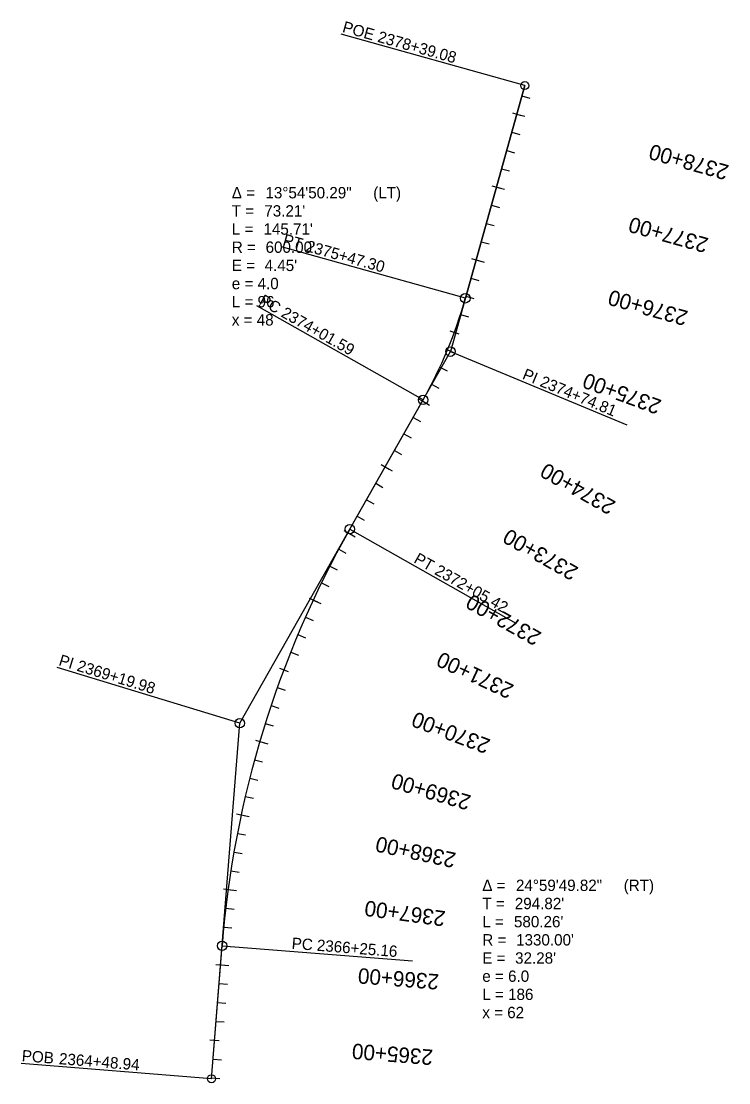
# Model space of a CAD drawing. Extents: x 20506511 to 20507445, y 7969244 to 7970646.
import ezdxf

# ---------------------------------------------------------------- set-up
doc = ezdxf.new("R2010")
doc.units = 0
for name, color, linetype in [('Alignment', 7, 'Continuous'), ('TextAlignment', 7, 'Continuous'), ('TextAlignmentLrg', 7, 'Continuous'), ('TextAlignmentSml', 7, 'Continuous')]:
    doc.layers.add(name, color=color, linetype=linetype)

msp = doc.modelspace()

# ---------------------------------------------------------------- linework, layer by layer
at = {"layer": 'Alignment'}
for p, q in [((20507175.7, 7970561.2), (20507077.5, 7970209.7)), ((20507175.7, 7970561.2), (20507097.2, 7970280.2)), ((20507097.2, 7970280.2), (20507175.7, 7970561.2)), ((20506799.4, 7969718.8), (20507077.5, 7970209.7)), ((20506944.7, 7969975.3), (20507041.4, 7970146)), ((20506762.1, 7969249.2), (20506799.4, 7969718.8)), ((20506762.1, 7969249.2), (20506776.1, 7969424.9)), ((20506762.1, 7969249.2), (20506776.1, 7969424.9))]:
    msp.add_line(p, q, dxfattribs=at)
for centre, radius, start, end in [((20506519.3, 7970441.7), 600, 330.4678, 344.3818), ((20506519.3, 7970441.7), 600, 330.4678, 344.3818), ((20508101.9, 7969319.7), 1330, 150.4678, 175.465), ((20508101.9, 7969319.7), 1330, 150.4678, 175.465)]:
    msp.add_arc(centre, radius, start, end, dxfattribs=at)
at = {"layer": 'TextAlignment'}
for p, q in [((20507175.7, 7970561.2), (20506933.1, 7970629)), ((20506933.1, 7970629), (20506933.1, 7970629)), ((20507097.2, 7970280.2), (20506854.5, 7970348)), ((20506854.5, 7970348), (20506854.5, 7970348)), ((20507041.4, 7970146), (20506822.1, 7970270.2)), ((20506822.1, 7970270.2), (20506822.1, 7970270.2)), ((20507077.5, 7970209.7), (20507310.2, 7970112.9)), ((20507310.2, 7970112.9), (20507310.2, 7970112.9)), ((20506944.7, 7969975.3), (20507164, 7969851.1)), ((20507164, 7969851.1), (20507164, 7969851.1)), ((20506799.4, 7969718.8), (20506558.4, 7969792.6)), ((20506558.4, 7969792.6), (20506558.4, 7969792.6)), ((20506776.1, 7969424.9), (20507027.3, 7969404.9)), ((20507027.3, 7969404.9), (20507027.3, 7969404.9)), ((20506762.1, 7969249.2), (20506510.9, 7969269.1)), ((20506510.9, 7969269.1), (20506510.9, 7969269.1))]:
    msp.add_line(p, q, dxfattribs=at)
for centre, radius in [((20507175.7, 7970561.2), 5.34), ((20507097.2, 7970280.2), 6.24), ((20507077.5, 7970209.7), 6.24), ((20507041.4, 7970146), 6.24), ((20506944.7, 7969975.3), 6.24), ((20506799.4, 7969718.8), 6.24), ((20506776.1, 7969424.9), 6.24), ((20506762.1, 7969249.2), 5.34)]:
    msp.add_circle(centre, radius, dxfattribs=at)
at = {"layer": 'TextAlignmentLrg'}
for p, q in [((20507165.2, 7970523.6), (20507175.7, 7970520.6)), ((20507138.3, 7970427.2), (20507148.8, 7970424.3)), ((20507111.4, 7970330.9), (20507121.9, 7970328)), ((20507076.9, 7970237.3), (20507088.4, 7970233.1)), ((20507040.6, 7970144.6), (20507050.1, 7970139.2)), ((20506991.3, 7970057.6), (20507000.8, 7970052.2)), ((20506942, 7969970.6), (20506951.6, 7969965.2)), ((20506896.4, 7969881.6), (20506906.3, 7969877)), ((20506851.9, 7969791.6), (20506863.3, 7969787.3)), ((20506825.8, 7969694.7), (20506836.3, 7969691.6)), ((20506801.3, 7969597.8), (20506812, 7969595.5)), ((20506784.1, 7969499.3), (20506794.9, 7969497.8)), ((20506774.1, 7969399.8), (20506785, 7969398.9)), ((20506760.1, 7969300.6), (20506772.3, 7969299.6))]:
    msp.add_line(p, q, dxfattribs=at)
at = {"layer": 'TextAlignmentSml'}
for p, q in [((20507172, 7970547.6), (20507182.5, 7970544.7)), ((20507159.3, 7970525.2), (20507171.1, 7970521.9)), ((20507158.5, 7970499.5), (20507169, 7970496.5)), ((20507151.8, 7970475.4), (20507162.3, 7970472.5)), ((20507145, 7970451.3), (20507155.5, 7970448.4)), ((20507132.4, 7970428.9), (20507144.2, 7970425.6)), ((20507131.6, 7970403.2), (20507142.1, 7970400.2)), ((20507124.8, 7970379.1), (20507135.4, 7970376.2)), ((20507118.1, 7970355), (20507128.6, 7970352.1)), ((20507105.5, 7970332.6), (20507117.3, 7970329.3)), ((20507104.6, 7970306.9), (20507115.2, 7970303.9)), ((20507097.9, 7970282.8), (20507108.4, 7970279.8)), ((20507090.8, 7970258.8), (20507101.2, 7970255.5)), ((20507076.9, 7970237.3), (20507088.4, 7970233.1)), ((20507073.6, 7970211.9), (20507083.7, 7970207.7)), ((20507063.5, 7970189), (20507073.4, 7970184.4)), ((20507052.5, 7970166.6), (20507062.2, 7970161.6)), ((20507035.3, 7970147.6), (20507045.9, 7970141.6)), ((20507028.3, 7970122.8), (20507037.8, 7970117.5)), ((20507016, 7970101.1), (20507025.5, 7970095.7)), ((20507003.6, 7970079.3), (20507013.1, 7970073.9)), ((20506986, 7970060.6), (20506996.6, 7970054.6)), ((20506979, 7970035.8), (20506988.5, 7970030.4)), ((20506966.7, 7970014.1), (20506976.2, 7970008.7)), ((20506954.3, 7969992.3), (20506963.8, 7969986.9)), ((20506936.7, 7969973.6), (20506947.4, 7969967.6)), ((20506930, 7969948.7), (20506939.6, 7969943.5)), ((20506918.4, 7969926.5), (20506928.1, 7969921.5)), ((20506907.2, 7969904.2), (20506917, 7969899.4)), ((20506890.9, 7969884.2), (20506902, 7969879)), ((20506886.1, 7969858.8), (20506896.1, 7969854.4)), ((20506876.2, 7969835.9), (20506886.2, 7969831.7)), ((20506866.7, 7969812.8), (20506876.8, 7969808.7)), ((20506851.9, 7969791.6), (20506863.3, 7969787.3)), ((20506849, 7969766), (20506859.3, 7969762.3)), ((20506840.8, 7969742.4), (20506851.2, 7969738.9)), ((20506833.1, 7969718.6), (20506843.5, 7969715.3)), ((20506820, 7969696.4), (20506831.7, 7969692.9)), ((20506819, 7969670.6), (20506829.6, 7969667.7)), ((20506812.7, 7969646.4), (20506823.2, 7969643.8)), ((20506806.7, 7969622.2), (20506817.4, 7969619.7)), ((20506795.3, 7969599), (20506807.3, 7969596.5)), ((20506796.3, 7969573.3), (20506807, 7969571.2)), ((20506791.8, 7969548.7), (20506802.5, 7969546.8)), ((20506787.7, 7969524), (20506798.5, 7969522.3)), ((20506778, 7969500.1), (20506790.1, 7969498.4)), ((20506780.9, 7969474.5), (20506791.8, 7969473.2)), ((20506778.3, 7969449.6), (20506789.1, 7969448.5)), ((20506776.1, 7969424.7), (20506786.9, 7969423.8)), ((20506768, 7969400.3), (20506780.2, 7969399.3)), ((20506772.1, 7969374.9), (20506783, 7969374)), ((20506770.1, 7969349.9), (20506781, 7969349.1)), ((20506768.1, 7969325), (20506779, 7969324.2)), ((20506760.1, 7969300.6), (20506772.3, 7969299.6)), ((20506764.2, 7969275.2), (20506775.1, 7969274.3)), ((20506762.2, 7969250.3), (20506773.1, 7969249.4))]:
    msp.add_line(p, q, dxfattribs=at)

# ---------------------------------------------------------------- texts
at = {"layer": 'TextAlignment'}
for s, rotation, p in [('POE ', 344.3818, (20506933.9, 7970632.2)), ('2378+39.08', 344.3818, (20506980.3, 7970619.2)), ('PT', 344.3818, (20506855.4, 7970351.2)), ('2375+47.30', 344.3818, (20506885.7, 7970342.7)), ('PC', 330.4678, (20506823.8, 7970273.1)), ('2374+01.59', 330.4678, (20506852.7, 7970256.6)), ('PI ', 337.4248, (20507171.4, 7970174.2)), ('2374+74.81', 337.4248, (20507194.5, 7970164.6)), ('PT', 330.4678, (20507028.1, 7969931.8)), ('2372+05.42', 330.4678, (20507055.5, 7969916.3)), ('PI ', 342.9664, (20506559.4, 7969795.7)), ('2369+19.98', 342.9664, (20506583.3, 7969788.4)), ('PC', 355.465, (20506867.5, 7969420.9)), ('2366+25.16', 355.465, (20506900.7, 7969418.3)), ('POB ', 355.465, (20506511.2, 7969272.4)), ('2364+48.94', 355.465, (20506560.3, 7969268.5))]:
    msp.add_text(s, height=15, rotation=rotation, dxfattribs=at).set_placement(p)
for s, p in [(' (LT)', (20506970, 7970412.2)), ('Δ = ', (20506788.9, 7970412.2)), ('13°54\'50.29"', (20506833.3, 7970412.2)), ('T = ', (20506788.9, 7970388.2)), ("73.21'", (20506831.8, 7970388.2)), ('L = ', (20506788.9, 7970364.2)), ("145.71'", (20506830.7, 7970364.2)), ('R = ', (20506788.9, 7970340.2)), ("600.00'", (20506833.5, 7970340.2)), ('E = ', (20506788.9, 7970316.2)), ("4.45'", (20506832.2, 7970316.2)), ('e = 4.0', (20506788.9, 7970292.2)), ('L = 96', (20506788.9, 7970268.2)), ('x = 48', (20506788.9, 7970244.2)), ('Δ = ', (20507119.6, 7969497.2)), ('24°59\'49.82"', (20507164, 7969497.2)), (' (RT)', (20507300.7, 7969497.2)), ("294.82'", (20507162.5, 7969473.2)), ('T = ', (20507119.6, 7969473.2)), ('L = ', (20507119.6, 7969449.2)), ("580.26'", (20507161.4, 7969449.2)), ('R = ', (20507119.6, 7969425.2)), ("1330.00'", (20507164.2, 7969425.2)), ('E = ', (20507119.6, 7969401.2)), ("32.28'", (20507162.9, 7969401.2)), ('e = 6.0', (20507119.6, 7969377.2)), ('L = 186', (20507119.6, 7969353.2)), ('x = 62', (20507119.6, 7969329.2))]:
    msp.add_text(s, height=15, dxfattribs=at).set_placement(p)
at = {"layer": 'TextAlignmentLrg'}
for s, rotation, p in [('2375+00', 159.8651, (20507357.5, 7970145.3)), ('2370+00', 159.3172, (20507131.6, 7969696.9)), ('2365+00', 175.465, (20507055.1, 7969287.4))]:
    msp.add_text(s, height=20.4, rotation=rotation, dxfattribs=at).set_placement(p)
at = {"layer": 'TextAlignmentSml'}
for s, rotation, p in [('2378+00', 164.3818, (20507446.3, 7970455.6)), ('2377+00', 164.3818, (20507419.4, 7970359.3)), ('2376+00', 164.3818, (20507392.4, 7970263)), ('2375+00', 159.8651, (20507357.5, 7970145.3)), ('2374+00', 150.4678, (20507297.1, 7970011)), ('2373+00', 150.4678, (20507247.8, 7969924)), ('2372+00', 150.7013, (20507199, 7969838)), ('2371+00', 155.0093, (20507162.7, 7969768.8)), ('2370+00', 159.3172, (20507131.6, 7969696.9)), ('2369+00', 163.6252, (20507106, 7969623)), ('2368+00', 167.9331, (20507086, 7969547.3)), ('2367+00', 172.2411, (20507071.8, 7969470.4)), ('2366+00', 175.465, (20507063, 7969387.1)), ('2365+00', 175.465, (20507055.1, 7969287.4))]:
    msp.add_text(s, height=20.4, rotation=rotation, dxfattribs=at).set_placement(p)

doc.saveas('drawing.dxf')
